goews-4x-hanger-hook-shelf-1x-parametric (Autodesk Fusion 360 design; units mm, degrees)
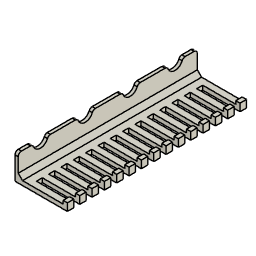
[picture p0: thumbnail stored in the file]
parameter "HookWidth" = 6
parameter "HookGapDepth" = 35
parameter "HookTipHeight" = 3
parameter "HookTipDepth" = 4
parameter "GapWidth" = 5.5429 (= "( 167.6 mm - ( HookWidth * QTYHooks ) ) / ( QTYHooks - 1 )")
base_feature "Base Feature" bodies "Quad Plate Blank"
work_plane "WorkPlane1" AlongDistance 4
delete_face "DeleteFace1"
sketch "Sketch1" plane through (0, 0, -108.1504) normal (0, 0, 1) x axis (-1, 0, 0)
  line L1 (-103.15, 20.8) -> (-103.15, -146.8)
  line L2 (-142.15, 20.8) -> (-103.15, 20.8)
  line L3 (-145.15, -143.8) -> (-145.15, 17.8)
  line L4 (-103.15, -146.8) -> (-142.15, -146.8)
  line L5 (-142.15, 20.8) -> (-103.15, 20.8)
  line L6 (-145.15, -143.8) -> (-145.15, 17.8)
  line L7 (-103.15, -146.8) -> (-142.15, -146.8)
  line L8 (-103.15, 20.8) -> (-103.15, -146.8)
  line L9 (-145.15, 20.8) -> (-145.15, 17.8)
  line L10 (-142.15, 20.8) -> (-145.15, 20.8)
  line L11 (-145.15, -146.8) -> (-145.15, -143.8)
  line L12 (-142.15, -146.8) -> (-145.15, -146.8)
  line L13 (-145.15, -146.8) -> (-142.15, -146.8)
  line L14 (-110.15, 14.8) -> (-145.15, 14.8)
  line L15 (-110.15, 9.2571) -> (-110.15, 14.8)
  line L16 (-145.15, 9.2571) -> (-110.15, 9.2571)
  line L17 (-145.15, 14.8) -> (-145.15, 9.2571)
  line L18 (-145.15, -2.2857) -> (-110.15, -2.2857)
  line L19 (-145.15, 3.2571) -> (-145.15, -2.2857)
  line L20 (-110.15, -2.2857) -> (-110.15, 3.2571)
  line L21 (-110.15, 3.2571) -> (-145.15, 3.2571)
  line L22 (-145.15, -13.8286) -> (-110.15, -13.8286)
  line L23 (-145.15, -8.2857) -> (-145.15, -13.8286)
  line L24 (-110.15, -13.8286) -> (-110.15, -8.2857)
  line L25 (-110.15, -8.2857) -> (-145.15, -8.2857)
  line L26 (-145.15, -25.3714) -> (-110.15, -25.3714)
  line L27 (-145.15, -19.8286) -> (-145.15, -25.3714)
  line L28 (-110.15, -25.3714) -> (-110.15, -19.8286)
  line L29 (-110.15, -19.8286) -> (-145.15, -19.8286)
  line L30 (-145.15, -36.9143) -> (-110.15, -36.9143)
  line L31 (-145.15, -31.3714) -> (-145.15, -36.9143)
  line L32 (-110.15, -36.9143) -> (-110.15, -31.3714)
  line L33 (-110.15, -31.3714) -> (-145.15, -31.3714)
  line L34 (-145.15, -48.4571) -> (-110.15, -48.4571)
  line L35 (-145.15, -42.9143) -> (-145.15, -48.4571)
  line L36 (-110.15, -48.4571) -> (-110.15, -42.9143)
  line L37 (-110.15, -42.9143) -> (-145.15, -42.9143)
  line L38 (-145.15, -60) -> (-110.15, -60)
  line L39 (-145.15, -54.4571) -> (-145.15, -60)
  line L40 (-110.15, -60) -> (-110.15, -54.4571)
  line L41 (-110.15, -54.4571) -> (-145.15, -54.4571)
  line L42 (-145.15, -71.5429) -> (-110.15, -71.5429)
  line L43 (-145.15, -66) -> (-145.15, -71.5429)
  line L44 (-110.15, -71.5429) -> (-110.15, -66)
  line L45 (-110.15, -66) -> (-145.15, -66)
  line L46 (-145.15, -83.0857) -> (-110.15, -83.0857)
  line L47 (-145.15, -77.5429) -> (-145.15, -83.0857)
  line L48 (-110.15, -83.0857) -> (-110.15, -77.5429)
  line L49 (-110.15, -77.5429) -> (-145.15, -77.5429)
  line L50 (-145.15, -94.6286) -> (-110.15, -94.6286)
  line L51 (-145.15, -89.0857) -> (-145.15, -94.6286)
  line L52 (-110.15, -94.6286) -> (-110.15, -89.0857)
  line L53 (-110.15, -89.0857) -> (-145.15, -89.0857)
  line L54 (-145.15, -106.1714) -> (-110.15, -106.1714)
  line L55 (-145.15, -100.6286) -> (-145.15, -106.1714)
  line L56 (-110.15, -106.1714) -> (-110.15, -100.6286)
  line L57 (-110.15, -100.6286) -> (-145.15, -100.6286)
  line L58 (-145.15, -117.7143) -> (-110.15, -117.7143)
  line L59 (-145.15, -112.1714) -> (-145.15, -117.7143)
  line L60 (-110.15, -117.7143) -> (-110.15, -112.1714)
  line L61 (-110.15, -112.1714) -> (-145.15, -112.1714)
  line L62 (-145.15, -129.2571) -> (-110.15, -129.2571)
  line L63 (-145.15, -123.7143) -> (-145.15, -129.2571)
  line L64 (-110.15, -129.2571) -> (-110.15, -123.7143)
  line L65 (-110.15, -123.7143) -> (-145.15, -123.7143)
  line L66 (-145.15, -140.8) -> (-110.15, -140.8)
  line L67 (-145.15, -135.2571) -> (-145.15, -140.8)
  line L68 (-110.15, -140.8) -> (-110.15, -135.2571)
  line L69 (-110.15, -135.2571) -> (-145.15, -135.2571)
  point P3 (-103.15, 20.8)
  point P8 (-103.15, 20.8)
  point P9 (-145.15, 20.8)
  point P15 (-145.15, 20.8)
  point P6 (-145.15, -143.8)
  point P16 (-145.15, -143.8)
  point P7 (-142.15, -146.8)
  point P18 (-142.15, -146.8)
  point P21 (-145.15, 14.8)
  point P4 (-142.15, 20.8)
  point P10 (-103.15, -146.8)
  point P23 (-110.15, 9.2571)
  point P24 (-145.15, 9.2571)
  point P22 (-110.15, 14.8)
  horizontal L5
  vertical L6
  horizontal L7
  vertical L8
  coincident P3 P8
  coincident P9 L5
  coincident P9 L6
  coincident P9 P15
  coincident P6 P16
  coincident P7 P18
  horizontal L14
  vertical L15
  horizontal L16
  vertical L17
  coincident L6 P21
  dimension "d10" distance P4 P7 = 167.6
  dimension "d26" distance P8 P9 = 42
  dimension "d27" distance P8 P10 = 167.6
  dimension "d35" distance P23 P24 = 35 (= "HookGapDepth")
  dimension "d36" distance L5 L14 = 6 (= "HookWidth")
  dimension "d37" distance P22 P23 = 5.5429 (= "( 167.6 mm - ( HookWidth * QTYHooks ) ) / ( QTYHooks - 1 )")
  dimension "d41" R-Pattern1-uDistance = 0
sketch "Sketch2" plane through (0, 0, -108.1504) normal (0, 0, 1) x axis (-1, 0, 0)
  line L1 (-145.15, -146.8) -> (-103.15, -146.8)
  line L2 (-145.15, 20.8) -> (-145.15, -146.8)
  line L3 (-103.15, 20.8) -> (-145.15, 20.8)
  line L4 (-103.15, -146.8) -> (-103.15, 20.8)
  line L5 (-141.15, 20.8) -> (-141.15, -146.8)
  point P2 (-103.15, -146.8)
  point P4 (-103.15, -146.8)
  point P8 (-141.15, -146.8)
  point P9 (-141.15, 20.8)
  point P5 (-145.15, -146.8)
  horizontal L1
  vertical L2
  horizontal L3
  vertical L4
  coincident P2 P4
  coincident L1 P8
  coincident L3 P9
  perpendicular L3 L5
  dimension "d43" distance P4 P5 = 42
  dimension "d44" distance L2 L5 = 4 (= "HookTipDepth")
extrude "Extrude5" add sketch "Sketch2" against normal blind 4
extrude "Extrude6" add sketch "Sketch2" profile of L1 L2 L3 L5 along normal blind 3 (= "HookTipHeight")
extrude "Extrude7" cut sketch "Sketch1" profile of L3 L6 L14 L15 L16 L17 L18 L19 L20 L21 L22 L23 L24 L25 L26 L27 L28 L29 L30 L31 L32 L33 L34 L35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 distance 30
named bodies: "Quad Plate Blank"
